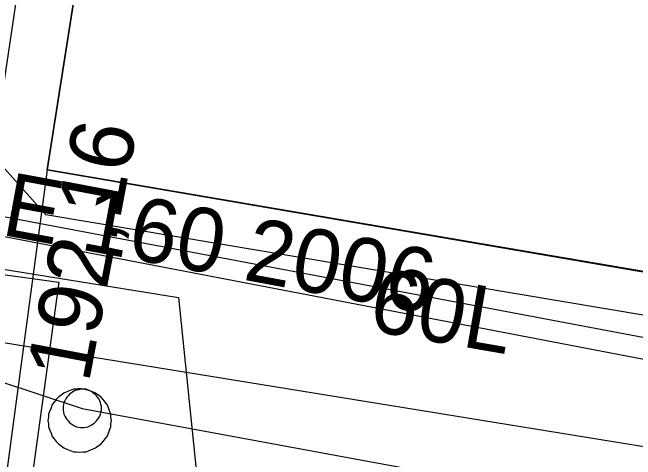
# Model space of a CAD drawing. Extents: x -746464 to -745690, y -1051581 to -1049993.
# Drawn here: x -746221.81 to -746212.02, y -1050948.29 to -1050941.27 of the extents above; entities that cross this region are included whole.
import ezdxf

# ---------------------------------------------------------------- set-up
doc = ezdxf.new("R2010")
doc.units = 0
for name, color, linetype in [('04_CETIN_sdelovaci_podzem', 7, 'Continuous'), ('37_TVNET_sdelovaci_televizni kabely', 7, 'Continuous'), ('48_Prazs_plynarenska_STL', 7, 'Continuous'), ('48_Prazs_plynarenska_STL_popisy', 7, 'Continuous'), ('51_PVaK_kanal_jednotna_overena poloha_rad', 7, 'Continuous'), ('51_PVaK_kanal_objekty', 7, 'Continuous'), ('51_PVaK_kanal_popisy', 7, 'Continuous'), ('51_PVaK_vodovod_NEPROVOZUJE PVK_neoverene poloha', 7, 'Continuous'), ('51_PVaK_vodovod_overena poloha_rad', 7, 'Continuous'), ('51_PVaK_vodovod_popisy', 7, 'Continuous'), ('55_PREdi_chranicky', 7, 'Continuous'), ('55_PREdi_NN', 7, 'Continuous')]:
    doc.layers.add(name, color=color, linetype=linetype)

msp = doc.modelspace()

# ---------------------------------------------------------------- linework, layer by layer
at = {"layer": '04_CETIN_sdelovaci_podzem'}
msp.add_lwpolyline([(-746208.47, -1050946.6), (-746221.28, -1050944.45), (-746222.06, -1050943.58), (-746222.34, -1050941.98), (-746214.81, -1050895.26)], dxfattribs=at)
at = {"layer": '37_TVNET_sdelovaci_televizni kabely'}
msp.add_lwpolyline([(-746222.7841, -1050936.3314), (-746222.7841, -1050944.3199), (-746195.372, -1050949.4906), (-746194.8251, -1050933.5135)], dxfattribs=at)
at = {"layer": '48_Prazs_plynarenska_STL'}
msp.add_lwpolyline([(-746223.4, -1050946.22), (-746203.02, -1050949.53), (-746187.08, -1050952.24), (-746178.97, -1050953.64), (-746169.78, -1050955.18), (-746157.4, -1050957.2), (-746140.96, -1050959.93), (-746135.46, -1050960.65)], dxfattribs=at)
at = {"layer": '51_PVaK_kanal_jednotna_overena poloha_rad'}
msp.add_line((-746227.16, -1050945.37), (-746220.71, -1050947.49), dxfattribs=at)
msp.add_lwpolyline([(-746220.71, -1050947.49), (-746206.238, -1050950.163), (-746204.566, -1050950.472), (-746195.224, -1050952.197), (-746185.292, -1050954.031), (-746183.62, -1050954.34)], dxfattribs=at)
at = {"layer": '51_PVaK_kanal_objekty'}
for points in [[(-746220.25, -1050947.68), (-746220.26, -1050947.63), (-746220.26, -1050947.58), (-746220.28, -1050947.53), (-746220.3, -1050947.48), (-746220.32, -1050947.43), (-746220.35, -1050947.39), (-746220.38, -1050947.35), (-746220.42, -1050947.31), (-746220.46, -1050947.28), (-746220.5, -1050947.25), (-746220.55, -1050947.23), (-746220.6, -1050947.21), (-746220.65, -1050947.19), (-746220.7, -1050947.19), (-746220.75, -1050947.18), (-746220.8, -1050947.19), (-746220.85, -1050947.19), (-746220.9, -1050947.21), (-746220.95, -1050947.23), (-746221, -1050947.25), (-746221.04, -1050947.28), (-746221.08, -1050947.31), (-746221.12, -1050947.35), (-746221.15, -1050947.39), (-746221.18, -1050947.43), (-746221.2, -1050947.48), (-746221.22, -1050947.53), (-746221.24, -1050947.58), (-746221.24, -1050947.63), (-746221.25, -1050947.68), (-746221.24, -1050947.73), (-746221.24, -1050947.78), (-746221.22, -1050947.83), (-746221.2, -1050947.88), (-746221.18, -1050947.93), (-746221.15, -1050947.97), (-746221.12, -1050948.01), (-746221.08, -1050948.05), (-746221.04, -1050948.08), (-746221, -1050948.11), (-746220.95, -1050948.13), (-746220.9, -1050948.15), (-746220.85, -1050948.17), (-746220.8, -1050948.17), (-746220.75, -1050948.18), (-746220.7, -1050948.17), (-746220.65, -1050948.17), (-746220.6, -1050948.15), (-746220.55, -1050948.13), (-746220.5, -1050948.11), (-746220.46, -1050948.08), (-746220.42, -1050948.05), (-746220.38, -1050948.01), (-746220.35, -1050947.97), (-746220.32, -1050947.93), (-746220.3, -1050947.88), (-746220.28, -1050947.83), (-746220.26, -1050947.78), (-746220.26, -1050947.73), (-746220.25, -1050947.68)], [(-746220.41, -1050947.49), (-746220.41, -1050947.46), (-746220.416, -1050947.43), (-746220.422, -1050947.4), (-746220.434, -1050947.37), (-746220.452, -1050947.34), (-746220.47, -1050947.316), (-746220.488, -1050947.292), (-746220.512, -1050947.268), (-746220.536, -1050947.25), (-746220.56, -1050947.232), (-746220.59, -1050947.214), (-746220.62, -1050947.202), (-746220.65, -1050947.196), (-746220.68, -1050947.19), (-746220.71, -1050947.19), (-746220.74, -1050947.19), (-746220.77, -1050947.196), (-746220.8, -1050947.202), (-746220.83, -1050947.214), (-746220.86, -1050947.232), (-746220.884, -1050947.25), (-746220.908, -1050947.268), (-746220.932, -1050947.292), (-746220.95, -1050947.316), (-746220.968, -1050947.34), (-746220.986, -1050947.37), (-746220.998, -1050947.4), (-746221.004, -1050947.43), (-746221.01, -1050947.46), (-746221.01, -1050947.49), (-746221.01, -1050947.52), (-746221.004, -1050947.55), (-746220.998, -1050947.58), (-746220.986, -1050947.61), (-746220.968, -1050947.64), (-746220.95, -1050947.664), (-746220.932, -1050947.688), (-746220.908, -1050947.712), (-746220.884, -1050947.73), (-746220.86, -1050947.748), (-746220.83, -1050947.766), (-746220.8, -1050947.778), (-746220.77, -1050947.784), (-746220.74, -1050947.79), (-746220.71, -1050947.79), (-746220.68, -1050947.79), (-746220.65, -1050947.784), (-746220.62, -1050947.778), (-746220.59, -1050947.766), (-746220.56, -1050947.748), (-746220.536, -1050947.73), (-746220.512, -1050947.712), (-746220.488, -1050947.688), (-746220.47, -1050947.664), (-746220.452, -1050947.64), (-746220.434, -1050947.61), (-746220.422, -1050947.58), (-746220.416, -1050947.55), (-746220.41, -1050947.52), (-746220.41, -1050947.49)]]:
    msp.add_lwpolyline(points, dxfattribs=at)
at = {"layer": '51_PVaK_vodovod_NEPROVOZUJE PVK_neoverene poloha'}
msp.add_line((-746201.61, -1050948.69), (-746224.044, -1050944.393), dxfattribs=at)
at = {"layer": '51_PVaK_vodovod_overena poloha_rad'}
msp.add_lwpolyline([(-746230.93, -1050943.85), (-746219.2, -1050945.75), (-746218.86, -1050949.07), (-746217.243, -1050949.372)], dxfattribs=at)
at = {"layer": '55_PREdi_chranicky'}
msp.add_lwpolyline([(-746221.895, -1050951.451), (-746222.885, -1050951.315), (-746222.07, -1050945.37), (-746221.08, -1050945.506), (-746221.895, -1050951.451)], close=True, dxfattribs=at)
at = {"layer": '55_PREdi_NN'}
for points in [[(-746174.518, -1050894.72), (-746175.58, -1050894.502), (-746213.602, -1050886.573), (-746219.211, -1050924.033), (-746222.128, -1050943.603), (-746222.661, -1050951.707), (-746224.213, -1050963.119), (-746219.87, -1050963.874), (-746219.349, -1050963.973)], [(-746221.26, -1050943.74), (-746215.343, -1050906.112), (-746213.545, -1050894.298)], [(-746185.318, -1050949.036), (-746185.457, -1050949.85), (-746221.258, -1050943.743), (-746218.566, -1050926.613), (-746217.175, -1050926.831)], [(-746221.26, -1050943.74), (-746222.29, -1050951.403), (-746224.286, -1050963.566)], [(-746221.26, -1050943.74), (-746202.514, -1050946.953), (-746187.107, -1050949.54), (-746184.174, -1050950.033), (-746166.055, -1050953.183), (-746155.124, -1050955.037)]]:
    msp.add_lwpolyline(points, dxfattribs=at)

# ---------------------------------------------------------------- texts
at = {"layer": '48_Prazs_plynarenska_STL_popisy'}
msp.add_text('STL PE 160 2006', height=1, rotation=349.48395, dxfattribs=at).set_placement((-746225.6558, -1050944.0809))
at = {"layer": '51_PVaK_kanal_popisy'}
msp.add_text('192,16', height=1, rotation=79.24686, dxfattribs=at).set_placement((-746220.608, -1050947.106))
at = {"layer": '51_PVaK_vodovod_popisy'}
msp.add_text('60L', height=1, rotation=350.15423, dxfattribs=at).set_placement((-746216.237, -1050946.26))

doc.saveas('drawing.dxf')
